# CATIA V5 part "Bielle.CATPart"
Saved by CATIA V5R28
Part number: Bielle
Bounding box of the stored display mesh (mm): x -2 to 2, y -5.361 to 5.361, z -5.302 to 34.5
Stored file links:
  D:\Back up\Mission d'enseignement\TP Catia\2 oct - Assemblage\Bielle.CATPart
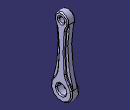
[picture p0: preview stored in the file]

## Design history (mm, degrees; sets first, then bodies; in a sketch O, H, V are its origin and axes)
Body1 (main body)
  Sketch1 on yz-plane, origin (0, 0, 0), H (0, 1, 0), V (0, 0, 1)
    arc A1 centre (0, 31) radius 3.5 from (3.4386, 30.3474) to (-3.4386, 30.3474) ccw
    point P1 (0, 31)
    circle A2 centre (0, 31) radius 1.5
    arc A3 centre (0, 0) radius 5.5 from (-5.2334, 1.6917) to (5.2334, 1.6917) ccw
    circle A4 centre (0, 0) radius 2.5
    arc A5 centre (-60.4214, 19.5323) radius 58 from (-5.2334, 1.6917) to (-3.4386, 30.3474) ccw
    arc A6 centre (60.4214, 19.5323) radius 58 from (3.4386, 30.3474) to (5.2334, 1.6917) ccw
    radius A1 = 3.5
    radius A2 = 1.5
    radius A4 = 2.5
    radius A3 = 5.5
    distance O P1 = 31
    radius A5 = 58
    radius A6 = 58
    coincidence: P1 V
    tangency: A6 A1, A6 A3, A5 A1, A5 A3
  Pad1: profile Sketch1, direction (1, 0, 0), length 2, mirrored extent
  Sketch2 on end face of Pad1, origin (2, 0, 0), H (0, 1, 0), V (0, 0, 1)
    axis line L1 (-2, 37.4958) -> (-2, -14.9149)
    arc A1 centre (-69.4107, 17.1332) radius 68 from (-2.0676, 7.7041) to (-2.0676, 26.5624) ccw
    point P4 (-2.0676, 7.7041)
    point P5 (-2.0676, 26.5624)
    arc A2 centre (-9, 25.5917) radius 7 from (-2.0676, 26.5623) to (-3.3153, 29.6764) ccw
    point P7 (-2.0676, 26.5623)
    point P8 (-3.3153, 29.6764)
    reference projected arc E1 centre (0, 31) radius 3.5 from (3.4386, 30.3474) to (-3.4386, 30.3474) ccw from edge [face of Pad1 from Sketch1.A1 | end face of Pad1]
    projected arc E2 centre (-60.4214, 19.5323) radius 58 from (-5.2334, 1.6917) to (-3.4386, 30.3474) ccw from edge [face of Pad1 from Sketch1.A5 | end face of Pad1]
    projected arc E3 centre (-60.4214, 19.5323) radius 58 from (-5.2334, 1.6917) to (-3.3153, 29.6764) ccw from edge [face of Pad1 from Sketch1.A5 | end face of Pad1]
    point P9 (-5.2334, 1.6917)
    point P10 (-3.4386, 30.3474)
    construction circle A3 centre (0, 0) radius 5.5
    arc A4 centre (-9, 8.6747) radius 7 from (-3.96, 3.8168) to (-2.0676, 7.704) ccw
    point P12 (-3.96, 3.8168)
    arc A5 centre (0, 0) radius 5.5 from (-3.96, 3.8169) to (-5.2334, 1.6917) ccw
    point P13 (-3.96, 3.8169)
    point P14 (-2.0676, 7.704)
    reference intersected line E4 through (0, 0) direction (0, 1) from zx-plane
    construction line L2 through (0, 0) direction (-1, 0)
    construction line L3 through (0, 0) direction (0, 1)
    point P18 (2.0676, 7.7041)
    point P19 (2.0676, 26.5624)
    point P20 (2.0676, 26.5623)
    point P21 (3.3153, 29.6764)
    point P22 (5.2334, 1.6917)
    point P23 (3.4386, 30.3474)
    point P24 (3.96, 3.8168)
    point P25 (3.96, 3.8169)
    point P26 (2.0676, 7.704)
    arc A6 centre (69.4107, 17.1332) radius 68 from (2.0676, 7.7041) to (2.0676, 26.5624) cw
    arc A7 centre (9, 25.5917) radius 7 from (2.0676, 26.5623) to (3.3153, 29.6764) cw
    arc A8 centre (9, 8.6747) radius 7 from (3.96, 3.8168) to (2.0676, 7.704) cw
    arc A9 centre (0, 0) radius 5.5 from (3.96, 3.8169) to (5.2334, 1.6917) cw
    construction arc A10 centre (60.4214, 19.5323) radius 58 from (5.2334, 1.6917) to (3.4386, 30.3474) cw
    arc A11 centre (60.4214, 19.5323) radius 58 from (5.2334, 1.6917) to (3.3153, 29.6764) cw
    distance V L1 = 2
    radius A1 = 68
    radius A2 = 7
    radius A4 = 7
    vertical: L1 V
    tangency: A2 L1, A2 E1, A1 A2, A3 E2, A4 A3, A4 L1, A1 A4, A5 E2
    coincidence: P8 E2, P13 A4, P14 A1, P4 A4, P7 A1, P5 A2, P12 A5
    symmetry: H L2 E4, V L3 E4, P4 P18 E4, P5 P19 E4, P7 P20 E4, P8 P21 E4, P9 P22 E4, P10 P23 E4, P12 P24 E4, P13 P25 E4, P14 P26 E4, A1 A6 E4, A2 A7 E4, A4 A8 E4, A5 A9 E4, E2 A10 E4, E2 A11 E4
  Pocket1: profile Sketch2, direction (-1, 0, 0), length 1
  Mirror1: of Pocket1, about yz-plane
  Chamfer1: length 0.5, angle 45, on end face of Pad1; start face of Pad1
